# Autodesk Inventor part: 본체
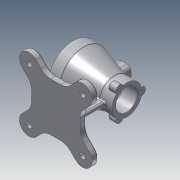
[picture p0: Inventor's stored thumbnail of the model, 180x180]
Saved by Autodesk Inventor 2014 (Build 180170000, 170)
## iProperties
Created: 2018-03
Part Number: 본체
Material: 알루미늄 6061
Document SubType Name: Modeling
Designer: net
Density: 2.71 g/cm^3
Appearance: 알루미늄 - 평지
Mass: 1015 g
Surface Area: 853.881 cm^2
Volume: 374.54 cm^3
Author: net
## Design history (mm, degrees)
sketch "스케치1"
  geometry: L1 (0, 0)-(0, 45); L2 (0, 45)-(20, 45); L3 (0, 0)-(100, 0); L4 (100, 0)-(100, 27.5); L5 (100, 27.5)-(77, 27.5); L6 (20, 45)-(77, 27.5); L7 (0, 0)-(0, -45); L8 (100, 0)-(100, -27.5)
  constraints: 16 end point, 3 perpendicular, 2 parallel, 1 vertical
  dimensions: "d0" = 45 distance of L1.start L1.end; "d1" = 20 distance of L1.end L2.end; "d3" = 100 distance of L1.start L3.end; "d4" = 27.5 distance of L3.end L4.end; "d5" = 23 distance of L4.end L5.end; "d118" = 45 distance of L1.start L7.end; "d119" = 90 distance of L7.end L1.end; "d120" = 27.5 distance of L3.end L8.end; "d121" = 55 distance of L4.end L8.end (derived)
revolve "회전1" sketch "스케치1" stored, may be unused: angle "d6" = 90 deg
sketch "스케치5"
  geometry: L1 (0, 0)-(50, 0); L2 (50, 0)-(50, 45); L3 (50, 45)-(62.5, 45); L4 (62.5, 45)-(62.5, 20); L5 (62.5, 20)-(50, 20); L6 (50, 20)-(50, 45); L7 (62.5, 20)-(37.5, 20); L8 (37.5, 20)-(37.5, 45); L9 (37.5, 45)-(62.5, 45); L10 (62.5, 45)-(62.5, 20)
  constraints: 20 end point, 4 parallel, 3 horizontal, 3 perpendicular
  dimensions: "d16" = 50 distance of L1.start L1.end; "d17" = 45 distance of L1.end L2.end; "d20" = 12.5 distance of L4.end L5.end; "d21" = 25 distance of L3.end L4.end; "d22" = 25 distance of L8.end L9.end
extrude "돌출4" join sketch "스케치5" stored distance "d23" = 25; taper "d24" = 0 deg
sketch "스케치2"
  geometry: C1 r 45 at (0, 0) reference; C2 r 35 at (0, 0)
  constraints: 1 centre point, 1 coincident
  dimensions: "d7" = 35 radius of C2
extrude "돌출1" cut sketch "스케치2" distance "d8" = 23; taper "d9" = 0 deg
sketch "스케치3"
  geometry: C1 r 35 at (0, 0) reference; C2 r 26 at (0, 0)
  constraints: 1 centre point, 1 coincident
  dimensions: "d10" = 26 radius of C2
extrude "돌출2" cut sketch "스케치3" distance "d11" = 47; taper "d12" = 0 deg
sketch "스케치4"
  geometry: C1 r 27.5 at (0, 0) reference; C2 r 20 at (0, 0)
  constraints: 1 centre point, 1 coincident
  dimensions: "d13" = 20 radius of C2
extrude "돌출3" cut sketch "스케치4" distance "d14" = 30; taper "d15" = 0 deg
sketch "스케치6"
  geometry: L1 (0, 25)-(25, 25); L2 (25, 25)-(25, 0); L3 (25, 0)-(0, 0); L4 (0, 0)-(0, 25); L5 (12.5, 12.5)-(20, 12.5); L6 (20, 12.5)-(20, 20); L7 (20, 20)-(12.5, 20); L8 (12.5, 20)-(12.5, 12.5); L9 (20, 20)-(5, 20); L10 (5, 20)-(5, 5); L11 (5, 5)-(20, 5); L12 (20, 5)-(20, 20); 1 further point
  constraints: 24 end point, 6 parallel, 3 horizontal, 3 perpendicular
  dimensions: "d25" = 7.5 distance of L7.end L6.end; "d26" = 7.5 distance of L6.end L5.end; "d27" = 15 distance of L11.end L10.end; "d28" = 15 distance of L10.end L9.end
extrude "돌출5" cut sketch "스케치6" distance "d29" = 30; taper "d30" = 0 deg
sketch "스케치7"
  geometry: L1 (0, 0)-(68.836, -39.743); L2 (0, 0)-(79.485, 0); L3 (0, 0)-(-52.99, -30.594); L4 (0, 0)-(61.188, 0); C1 r 7 at (0, 27.5); C2 r 20 at (0, 0) reference; 1 further point
  constraints: 8 end point, 2 equal length, 2 horizontal, 1 centre point, 1 vertical alignment, 1 other
  dimensions: "d31" = 7 radius of C1; "d116" = 30 deg angle of L1 L2; "d117" = 150 deg angle of L3 L4
extrude "돌출6" join sketch "스케치7" distance "d32" = 15; taper "d33" = 0 deg
sketch "스케치8"
  geometry: A1 r 7 centre (0, 0) between (6.943, -0.891) and (-6.943, -0.891) reference; A2 r 7 centre (-23.816, -41.25) between (-26.516, -34.792) and (-19.573, -46.817) reference; A3 r 7 centre (23.816, -41.25) between (19.573, -46.817) and (26.516, -34.792) reference; 3 further points
  constraints: 3 coincident
hole "구멍1" sketch "스케치8" at (0, 0), (-23.816, -41.25), (23.816, -41.25) diameter "d37" = 3.242; stored, may be unused: countersink angle "d41" = 90 deg, drill point angle "d43" = 118 deg; dims "d38" = 9, "d39" = 4, "d40" = 2, "d42" = 11
node "작업 평면1"
sketch "스케치10"
  geometry: L1 (-42.5, -7.5)-(-42.5, 7.5) reference; L2 (-42.5, 7.5)-(-57.5, 7.5) reference; L3 (-57.5, 7.5)-(-57.5, -7.5) reference; L4 (-57.5, -7.5)-(-42.5, -7.5) reference; L5 (-70, 26)-(-70, -26) reference; L6 (-23, 26)-(-23, -26) reference; L7 (-50, 0)-(-46, 0); L8 (-46, 0)-(-46, 24); L9 (-46, 24)-(-50, 24); L10 (-50, 24)-(-50, 0); L11 (-46, 24)-(-54, 24); L12 (-54, 24)-(-54, -24); L13 (-54, -24)-(-46, -24); L14 (-46, -24)-(-46, 24); 1 further point
  constraints: 16 end point, 4 parallel, 2 horizontal, 2 perpendicular
  dimensions: "d45" = 4 distance of L9.end L8.end; "d46" = 24 distance of L8.end L7.end; "d47" = 8 distance of L13.end L12.end; "d48" = 48 distance of L12.end L11.end
extrude "돌출7" join sketch "스케치10" stored distance "d49" = 15; taper "d50" = 0 deg
sketch "스케치11"
  geometry: L1 (95, 0)-(95, 45); L2 (95, 45)-(50, 45); L3 (95, 45)-(5, 45); L4 (5, 45)-(5, -45); L5 (5, -45)-(95, -45); L6 (95, -45)-(95, 45); 1 further point
  constraints: 12 end point, 2 parallel, 1 horizontal, 1 perpendicular
  dimensions: "d51" = 45 distance of L2.end L1.end; "d52" = 45 distance of L1.end L1.start; "d53" = 90 distance of L5.end L4.end; "d54" = 90 distance of L4.end L3.end
extrude "돌출8" join sketch "스케치11" distance "d55" = 12; taper "d56" = 0 deg
sketch "스케치12"
  geometry: L1 (50, 0)-(99.497, 49.497); L2 (50, 0)-(120, 0); L3 (50, 0)-(0.503, -49.497); L4 (50, 0)-(99.497, -49.497); L5 (50, 0)-(0.503, 49.497); L6 (-12.225, 36.77)-(86.77, -62.225); L7 (13.23, 62.225)-(112.225, -36.77); L8 (86.77, 62.225)-(-12.225, -36.77); L9 (112.225, 36.77)-(13.23, -62.225); A1 r 18 centre (99.497, 49.497) between (86.77, 62.225) and (112.225, 36.77); A2 r 18 centre (0.503, -49.497) between (-12.225, -36.77) and (13.23, -62.225); A3 r 18 centre (99.497, -49.497) between (86.77, -62.225) and (112.225, -36.77); A4 r 18 centre (0.503, 49.497) between (-12.225, 36.77) and (13.23, 62.225); 1 further point
  constraints: 18 end point, 8 point on circle, 6 tangent, 5 coincident, 4 centre point, 4 equal length, 1 horizontal, 1 perpendicular
  dimensions: "d57" = 70 distance of L1.start L1.end; "d58" = 45 deg angle of L2 L1; "d59" = 18 radius of A1; "d60" = 18 radius of A2; "d61" = 18 radius of A3; "d62" = 18 radius of A4
extrude "돌출9" join sketch "스케치12" distance "d63" = 12; taper "d64" = 0 deg
sketch "스케치13"
  geometry: C1 r 5 at (0.503, 49.497); C2 r 5 at (99.497, 49.497); C3 r 5 at (99.497, -49.497); C4 r 5 at (0.503, -49.497); A1 r 18 centre (0.503, -49.497) between (-12.225, -36.77) and (13.23, -62.225) reference; A2 r 18 centre (99.497, -49.497) between (86.77, -62.225) and (112.225, -36.77) reference; A3 r 18 centre (99.497, 49.497) between (112.225, 36.77) and (86.77, 62.225) reference; A4 r 18 centre (0.503, 49.497) between (13.23, 62.225) and (-12.225, 36.77) reference; 1 further point
  constraints: 4 centre point, 4 coincident
  dimensions: "d65" = 5 radius of C1; "d66" = 5 radius of C2; "d67" = 5 radius of C3; "d68" = 5 radius of C4
extrude "돌출10" cut sketch "스케치13" distance "d69" = 12; taper "d70" = 0 deg
feature "면 기울기2" dims angle "d113" = 5 deg
feature "면 기울기3" dims angle "d114" = 5 deg
sketch "스케치14"
  geometry: L1 (69.544, 45)-(30.456, 45) reference; L2 (50, 0)-(13, 0); L3 (13, 0)-(87, 0); L4 (13, 0)-(87, 0); L5 (87, 0)-(87, 4); L6 (87, 4)-(13, 4); L7 (13, 4)-(13, 0); L8 (13, 4)-(87, 4); L9 (87, 4)-(87, -4); L10 (87, -4)-(13, -4); L11 (13, -4)-(13, 4); 1 further point
  constraints: 20 end point, 5 parallel, 2 horizontal, 2 perpendicular, 1 collinear
  dimensions: "d71" = 37 distance of L2.start L2.end; "d72" = 74 distance of L2.end L3.end; "d73" = 4 distance of L5.end L4.end; "d74" = 8 distance of L8.end L9.end
extrude "돌출11" join sketch "스케치14" stored distance "d75" = 12; taper "d76" = 0 deg
sketch "스케치15" dims "d77" = 40
  geometry: C1 r 45 at (0, 0) reference; 2 further points
  constraints: 1 coincident, 1 vertical alignment, 2 other
hole "구멍2" sketch "스케치15" at (0, 40) diameter "d78" = 3.242; stored, may be unused: countersink angle "d82" = 90 deg, drill point angle "d84" = 118 deg; dims "d79" = 9, "d80" = 4, "d81" = 2, "d83" = 11
fillet "모깎기1" dims "d88" = 3
chamfer "모따기1" distance "d89" = 1; stored, may be unused: second distance "d90" = 2, angle "d91" = 45 deg
fillet "모깎기2" dims "d92" = 3
fillet "모깎기3" dims "d93" = 3
fillet "모깎기4" dims "d94" = 3
fillet "모깎기6" dims "d96" = 3
fillet "모깎기7" dims "d97" = 8
fillet "모깎기8" dims "d98" = 3
fillet "모깎기9" dims "d99" = 1
fillet "모깎기12" dims "d115" = 25
chamfer "모따기2" distance "d100" = 3; stored, may be unused: second distance "d101" = 2, angle "d102" = 45 deg
fillet "모깎기10" dims "d103" = 1
fillet "모깎기11" dims "d104" = 3
sketch "스케치16"
  geometry: L1 (92, 9.189)-(92, -9.189) reference; L2 (50, 0)-(50, -35); L3 (95, -9.189)-(95, 9.189) reference; L4 (95, 0)-(50, 0); 6 further points
  constraints: 4 end point, 1 coincident, 1 midpoint, 1 parallel, 1 perpendicular, 1 other
  dimensions: "d105" = 35 distance of L2.start L2.end; "d106" = 45 distance of L4.start L2.start
feature "엠보싱1" sketch "스케치16" dims "d0" = 45, "d1" = 20, "d3" = 100, "d4" = 27.5, "d5" = 23, "d107" = 0.5, "d108" = 0, "d118" = 45, "d119" = 90, "d120" = 27.5, "d121" = 55 (derived)
chamfer "모따기3" distance "d109" = 1; stored, may be unused: second distance "d110" = 2, angle "d111" = 45 deg
node "솔리드1"
pattern_circular "원형 패턴1" dims angle "d35" = 360 deg
pattern_circular "원형 패턴2" dims angle "d86" = 360 deg
node "투영된 루프1"
other parameters: "d44" = -82
